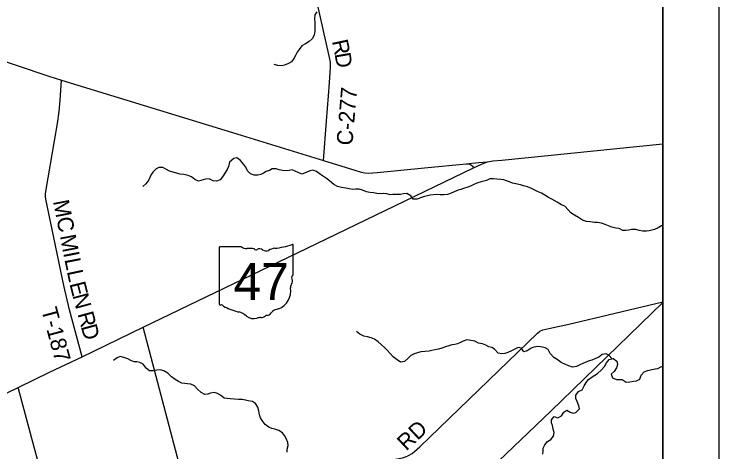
# Model space of a CAD drawing. Extents: x 0 to 34, y 0 to 22.
# Drawn here: x 7.746 to 9, y 18.489 to 19.269 of the extents above; entities that cross this region are included whole.
import ezdxf

# ---------------------------------------------------------------- set-up
doc = ezdxf.new("R2010")
doc.units = 0
for name, color, linetype in [('GM_X_Corporation', 7, 'Continuous'), ('GM_X_County_Road', 7, 'Continuous'), ('GM_X_County_Road_Text', 7, 'Continuous'), ('GM_X_Minor_River', 7, 'Continuous'), ('GM_X_Rail_Line', 7, 'Continuous'), ('GM_X_State_Location', 7, 'Continuous'), ('GM_X_State_Route', 7, 'Continuous'), ('GM_X_State_Shield', 7, 'Continuous'), ('GM_X_Township_Road', 7, 'Continuous'), ('GM_X_Township_Road_Text', 7, 'Continuous'), ('SH_Data', 7, 'Continuous')]:
    doc.layers.add(name, color=color, linetype=linetype)

msp = doc.modelspace()

# ---------------------------------------------------------------- linework, layer by layer
at = {"layer": 'GM_X_Corporation'}
msp.add_lwpolyline([(2.7052, 14.1), (8.9, 14.1), (8.9, 20.9), (3.3687, 20.9)], dxfattribs=at)
at = {"layer": 'GM_X_County_Road'}
msp.add_line((8.0553, 18.4096), (7.9758, 18.7116), dxfattribs=at)
for points in [[(8.2963, 19.0086), (8.302, 19.0784), (8.3053, 19.1235), (8.3071, 19.1474), (8.3085, 19.1645), (8.309, 19.1752), (8.3086, 19.1834), (8.3071, 19.1921), (8.2781, 19.3218), (8.2222, 19.5554), (8.2211, 19.5604), (8.2198, 19.5642), (8.2177, 19.5688), (8.2146, 19.5731), (8.2097, 19.5775), (8.182, 19.5969), (8.1775, 19.6005), (8.1738, 19.605), (8.1718, 19.6086), (8.1697, 19.6132), (8.1473, 19.6984), (8.1296, 19.7719)], [(7.5127, 19.2579), (7.8078, 19.1585), (7.8301, 19.1512), (8.1499, 19.0536), (8.2963, 19.0086), (8.3523, 18.9913), (8.3632, 18.9879), (8.37, 18.9865), (8.3767, 18.9857), (8.3918, 18.9869), (8.4764, 18.9952), (8.5503, 19.0026), (8.5542, 19.0026), (8.5566, 19.0019), (8.5586, 19.0009), (8.5604, 18.9996), (8.5617, 18.9983), (8.5629, 18.9963), (8.5634, 18.9953)], [(8.5503, 19.0026), (8.5721, 19.0049), (8.5881, 19.0061)], [(8.0553, 18.4096), (8.4281, 18.4771), (8.437, 18.4792), (8.4423, 18.4808), (8.4474, 18.4831), (8.4542, 18.4866), (8.4585, 18.4901), (8.468, 18.4988), (8.6772, 18.7011), (8.6815, 18.7044), (8.6868, 18.7067), (8.6976, 18.7094), (8.7166, 18.7135), (8.7303, 18.7166), (8.9, 18.7566)], [(7.9482, 17.7373), (7.9476, 17.7398), (7.9368, 17.7869), (7.8597, 18.12), (7.8214, 18.2877), (7.8179, 18.3039), (7.8159, 18.3198), (7.8153, 18.3322), (7.8149, 18.3594), (7.8146, 18.3659), (7.8137, 18.3742), (7.8123, 18.3822), (7.8085, 18.3979), (7.8046, 18.4124), (7.7817, 18.4979), (7.7531, 18.6039)]]:
    msp.add_lwpolyline(points, dxfattribs=at)
at = {"layer": 'GM_X_Minor_River'}
msp.add_line((8.9, 18.8932), (8.8979, 18.892), dxfattribs=at)
for points in [[(8.2843, 19.2733), (8.2809, 19.2676), (8.2805, 19.2604), (8.2812, 19.2534), (8.2812, 19.2465), (8.281, 19.2386), (8.2796, 19.2319), (8.2764, 19.2253), (8.2712, 19.2202), (8.2644, 19.216), (8.258, 19.2125), (8.253, 19.206), (8.2498, 19.2011), (8.2467, 19.1952), (8.2439, 19.1901), (8.2393, 19.1843), (8.2342, 19.1811), (8.2268, 19.1783), (8.2216, 19.1769), (8.215, 19.1777), (8.2086, 19.1795)], [(8.2774, 18.991), (8.2723, 18.9899), (8.2656, 18.9868), (8.2581, 18.9842), (8.2514, 18.9869), (8.2458, 18.9896), (8.2407, 18.9915), (8.2353, 18.9908), (8.2302, 18.9902), (8.2236, 18.9906), (8.2177, 18.9916), (8.2122, 18.9935), (8.205, 18.9935), (8.2003, 18.9905), (8.1944, 18.989), (8.1895, 18.9856), (8.1847, 18.9836), (8.1798, 18.9823), (8.1732, 18.9823), (8.1668, 18.9848), (8.1613, 18.9903), (8.1585, 18.9964), (8.1547, 19.0011), (8.1487, 19.0084), (8.1422, 19.0131), (8.1369, 19.012), (8.1293, 19.0056), (8.1274, 18.9978), (8.1249, 18.9923), (8.1211, 18.9859), (8.1169, 18.9793), (8.1123, 18.9738), (8.1061, 18.9714), (8.0998, 18.9725), (8.093, 18.9756), (8.0866, 18.9752), (8.0737, 18.9719), (8.0675, 18.9746), (8.0618, 18.9793), (8.0554, 18.9816), (8.048, 18.9832), (8.0412, 18.984), (8.0349, 18.9857), (8.029, 18.9876), (8.0224, 18.9897), (8.0169, 18.9926), (8.0103, 18.9962), (8.0037, 18.9961), (7.9988, 18.9934), (7.9934, 18.9885), (7.99, 18.9834), (7.9858, 18.9737), (7.9803, 18.9671), (7.9748, 18.962)], [(8.8979, 18.892), (8.8919, 18.8884), (8.8856, 18.8854), (8.8807, 18.8841), (8.8759, 18.8831), (8.8712, 18.8826), (8.8646, 18.8824), (8.8581, 18.8838), (8.8519, 18.8857), (8.8447, 18.8853), (8.8398, 18.8844), (8.8341, 18.8835), (8.8292, 18.8835), (8.8225, 18.8871), (8.8165, 18.8877), (8.8095, 18.8895), (8.8036, 18.8921), (8.7979, 18.8946), (8.7913, 18.8967), (8.7837, 18.8979), (8.7788, 18.8979), (8.7716, 18.8989), (8.7642, 18.8999), (8.7572, 18.9024), (8.7499, 18.9071), (8.7431, 18.9112), (8.7368, 18.9154), (8.7319, 18.9207), (8.7259, 18.9268), (8.7198, 18.9296), (8.7121, 18.9342), (8.7028, 18.9396), (8.6966, 18.9426), (8.6905, 18.9468), (8.6845, 18.9501), (8.6783, 18.9528), (8.6711, 18.9562), (8.6656, 18.9589), (8.6597, 18.9614), (8.6523, 18.9635), (8.6472, 18.9648), (8.6385, 18.9668), (8.6329, 18.9681), (8.6272, 18.9702), (8.6223, 18.9723), (8.6173, 18.9737), (8.6117, 18.9748), (8.6048, 18.9754), (8.599, 18.976), (8.5923, 18.9755), (8.5863, 18.973), (8.5772, 18.9706), (8.5694, 18.9682), (8.5639, 18.9657), (8.558, 18.9627), (8.5533, 18.961), (8.5457, 18.9588), (8.5408, 18.9569), (8.5358, 18.9554), (8.529, 18.9526), (8.5222, 18.9494), (8.517, 18.9479), (8.5108, 18.9472), (8.5042, 18.9472), (8.4983, 18.9478), (8.4918, 18.9472), (8.4865, 18.9465), (8.4814, 18.9456), (8.4761, 18.9445), (8.4691, 18.9422), (8.4628, 18.9394), (8.4562, 18.9396), (8.4517, 18.9457), (8.4445, 18.9495), (8.439, 18.9492), (8.4337, 18.948), (8.4269, 18.9479), (8.4199, 18.9479), (8.4148, 18.9475), (8.4093, 18.9489), (8.4034, 18.9495), (8.3981, 18.9491), (8.3911, 18.9497), (8.3854, 18.9511), (8.3786, 18.9513), (8.3727, 18.9528), (8.3657, 18.9553), (8.3599, 18.9573), (8.3534, 18.9573), (8.3485, 18.9569), (8.3419, 18.9577), (8.336, 18.9594), (8.3286, 18.9606), (8.3214, 18.9621), (8.3146, 18.9658), (8.3069, 18.9723), (8.3016, 18.9763), (8.2967, 18.9801), (8.2912, 18.9837), (8.284, 18.9891), (8.2774, 18.991)], [(8.8102, 18.6555), (8.804, 18.6616), (8.7991, 18.6639), (8.7923, 18.6628), (8.7862, 18.6583), (8.7794, 18.6555), (8.7741, 18.653), (8.7676, 18.6508), (8.7623, 18.6489), (8.7576, 18.647), (8.7525, 18.6446), (8.7468, 18.6414), (8.7394, 18.6406), (8.7329, 18.6426), (8.7269, 18.6449), (8.7193, 18.6489), (8.7121, 18.6538), (8.7061, 18.6575), (8.6997, 18.6649), (8.6959, 18.6717), (8.6906, 18.6748), (8.6829, 18.6765), (8.678, 18.6769), (8.6707, 18.676), (8.666, 18.6743), (8.659, 18.6694), (8.6527, 18.6677), (8.649, 18.6744), (8.6427, 18.6752), (8.638, 18.6731), (8.6309, 18.6693), (8.6243, 18.6663), (8.619, 18.6646), (8.6137, 18.6639), (8.6071, 18.6654), (8.6008, 18.6723), (8.5957, 18.6754), (8.5908, 18.6765), (8.5853, 18.6794), (8.5795, 18.6817), (8.5723, 18.6834), (8.5659, 18.6865), (8.5585, 18.688), (8.5515, 18.689), (8.545, 18.6869), (8.5401, 18.6843), (8.5351, 18.6822), (8.5302, 18.6809), (8.5245, 18.68), (8.5194, 18.6785), (8.5135, 18.6766), (8.5069, 18.674), (8.5008, 18.6725), (8.4944, 18.6712), (8.4891, 18.6699), (8.4843, 18.6688), (8.4768, 18.6682), (8.4696, 18.6675), (8.4637, 18.666), (8.4568, 18.6634), (8.4521, 18.6613), (8.4464, 18.6558), (8.4405, 18.6504), (8.4333, 18.6494), (8.4273, 18.6533), (8.4206, 18.6586), (8.415, 18.6647), (8.4095, 18.6708), (8.4048, 18.6757), (8.3999, 18.6803), (8.3939, 18.6855), (8.3871, 18.6904), (8.3812, 18.6927), (8.3746, 18.6946), (8.3679, 18.6956), (8.3608, 18.6994), (8.3549, 18.7038)], [(8.2317, 18.489), (8.2317, 18.4943), (8.2333, 18.5008), (8.2327, 18.5065), (8.2301, 18.5133), (8.2273, 18.5184), (8.2233, 18.5232), (8.2167, 18.5274), (8.2099, 18.5301), (8.2042, 18.5312), (8.1991, 18.5333), (8.1925, 18.5385), (8.1872, 18.5455), (8.1842, 18.5503), (8.1825, 18.5556), (8.1814, 18.5626), (8.1797, 18.5689), (8.1752, 18.5754), (8.1699, 18.5792), (8.1625, 18.5805), (8.1576, 18.5815), (8.1517, 18.5827), (8.1453, 18.5829), (8.1381, 18.5833), (8.1305, 18.5841), (8.125, 18.5843), (8.1197, 18.5851), (8.1133, 18.5906), (8.108, 18.5935), (8.1016, 18.5954), (8.0955, 18.5943), (8.0904, 18.5922), (8.0855, 18.5917), (8.0789, 18.5953), (8.0723, 18.6012), (8.0668, 18.6069), (8.0604, 18.6102), (8.0543, 18.6108), (8.0494, 18.6112), (8.0445, 18.6119), (8.0384, 18.6146), (8.0327, 18.6184), (8.0261, 18.6234), (8.0195, 18.6297), (8.0125, 18.6341), (8.0059, 18.6358), (7.9997, 18.6353), (7.9938, 18.6338), (7.987, 18.6336), (7.9811, 18.6386), (7.9756, 18.6458), (7.9694, 18.6485), (7.9645, 18.6496), (7.9596, 18.6497), (7.9533, 18.6523), (7.948, 18.6554), (7.9414, 18.6575), (7.9346, 18.6591), (7.9295, 18.657), (7.9226, 18.6523)], [(8.6869, 18.4855), (8.6871, 18.4912), (8.6875, 18.4959), (8.6901, 18.5022), (8.6951, 18.5078), (8.7012, 18.5114), (8.7059, 18.5173), (8.7069, 18.5239), (8.7052, 18.53), (8.7037, 18.5366), (8.702, 18.5414), (8.7023, 18.5463), (8.7068, 18.5526), (8.7134, 18.5501), (8.7201, 18.5538), (8.7239, 18.5605), (8.7296, 18.5637), (8.7356, 18.5604), (8.7408, 18.5587), (8.7457, 18.5598), (8.7518, 18.5664), (8.7508, 18.5717), (8.7477, 18.579), (8.7452, 18.5843), (8.7456, 18.5907), (8.75, 18.5972), (8.7568, 18.6002), (8.7601, 18.607), (8.7641, 18.613), (8.7679, 18.6182), (8.7742, 18.6232), (8.7793, 18.6263), (8.784, 18.6293), (8.7903, 18.6349), (8.7964, 18.6414), (8.8002, 18.648), (8.8048, 18.6541), (8.8116, 18.6559), (8.8182, 18.6512), (8.8193, 18.6451), (8.818, 18.6392), (8.8136, 18.6328), (8.8083, 18.6277), (8.8109, 18.6214), (8.8175, 18.6183), (8.8224, 18.6187), (8.8281, 18.6185), (8.8349, 18.6139), (8.8414, 18.6141), (8.8482, 18.6156), (8.8535, 18.6163), (8.8592, 18.6193), (8.8615, 18.6261), (8.8672, 18.6322), (8.8736, 18.6346)], [(8.8736, 18.6346), (8.8805, 18.6363), (8.8865, 18.6372), (8.8913, 18.6383), (8.8964, 18.641), (8.9, 18.6422)]]:
    msp.add_lwpolyline(points, dxfattribs=at)
at = {"layer": 'GM_X_Rail_Line'}
msp.add_lwpolyline([(5.2658, 15.2105), (5.3357, 15.2914), (5.4094, 15.3777), (5.4899, 15.4707), (5.6406, 15.6155), (5.8342, 15.8017), (6.1881, 16.1426), (6.4582, 16.4022), (6.7352, 16.6681), (7.0136, 16.9364), (7.2435, 17.1561), (7.4421, 17.3509), (7.6263, 17.5265), (7.9296, 17.8183), (8.0773, 17.9623), (8.4366, 18.3089), (8.7009, 18.5622), (8.9, 18.7553)], dxfattribs=at)
at = {"layer": 'GM_X_State_Route'}
msp.add_lwpolyline([(7.6544, 18.5581), (7.6984, 18.5781), (7.7531, 18.6039), (7.8091, 18.6312), (7.8668, 18.6586), (7.9758, 18.7116), (8.2503, 18.8438), (8.5634, 18.9953), (8.5774, 19.0021), (8.5832, 19.0045), (8.5881, 19.0061), (8.5979, 19.0076), (8.6135, 19.0091), (8.9, 19.038)], dxfattribs=at)
at = {"layer": 'GM_X_State_Shield'}
for p, q in [((8.1105, 18.8531), (8.1105, 18.753)), ((8.1504, 18.8548), (8.1118, 18.8548)), ((8.2424, 18.8049), (8.2424, 18.8573)), ((8.2424, 18.805), (8.2424, 18.8049))]:
    msp.add_line(p, q, dxfattribs=at)
for centre, radius, start, end in [((8.112, 18.8533), 0.00153, 98.1301, 188.1301), ((8.1596, 18.8664), 0.0148, 231.6195, 271.1119), ((8.1646, 18.7986), 0.0532, 80.4867, 94.9883), ((8.1766, 18.8538), 0.00427, 219.7921, 297.1024), ((8.1829, 18.8422), 0.00889, 54.4667, 119.1411), ((8.2132, 18.8242), 0.0281, 97.3462, 120.7689), ((8.1954, 18.9912), 0.1398, 275.8445, 288.9065), ((8.2409, 18.8575), 0.00147, 351.8621, 97.738), ((8.1944, 18.8581), 0.0107, 233.8562, 294.8282), ((8.242, 18.8011), 0.00227, 107.944, 210.337), ((8.2276, 18.7945), 0.0136, 340.033, 23.6496), ((8.2408, 18.8047), 0.00157, 289.6038, 7.7341), ((8.2476, 18.783), 0.00992, 136.8065, 186.9296), ((8.2032, 18.7764), 0.035, 292.3089, 8.9858), ((8.1121, 18.7528), 0.00154, 171.9584, 258.3066), ((8.1123, 18.763), 0.0118, 267.339, 280.6039), ((8.1147, 18.7472), 0.00424, 29.7484, 93.2717), ((8.1682, 18.8371), 0.101, 240.4129, 257.1985), ((8.1381, 18.7081), 0.0316, 47.1842, 75.836), ((8.218, 18.7249), 0.0192, 94.4031, 142.5768), ((8.1723, 18.7468), 0.02, 230.7004, 286.2918), ((8.1839, 18.7122), 0.0165, 85.6951, 111.2099), ((8.1853, 18.7393), 0.0107, 268.777, 315.5493), ((8.195, 18.7296), 0.00301, 65.7517, 132.6484), ((8.1937, 18.7433), 0.0113, 282.8732, 323.2771)]:
    msp.add_arc(centre, radius, start, end, dxfattribs=at)
at = {"layer": 'GM_X_Township_Road'}
msp.add_lwpolyline([(7.8668, 18.6586), (7.8446, 18.7427), (7.8341, 18.7856), (7.8023, 18.9393), (7.8018, 18.9436), (7.802, 18.9489), (7.803, 18.957), (7.8176, 19.0433), (7.823, 19.0745), (7.8263, 19.0959), (7.8281, 19.1157), (7.8301, 19.1512)], dxfattribs=at)
at = {"layer": 'SH_Data'}
for p, q in [((9, 21), (9, 14)), ((8.9, 20.9), (8.9, 14.1))]:
    msp.add_line(p, q, dxfattribs=at)

# ---------------------------------------------------------------- texts
at = {"layer": 'GM_X_County_Road_Text'}
for s, height, rotation, p in [('R', 0.0284, 282.0631, (8.3112, 19.2209)), ('D', 0.0284, 279.7438, (8.316, 19.1984)), ('C-277', 0.02841, 85.3045, (8.3478, 19.0345)), ('RD', 0.02841, 43.0911, (8.4437, 18.4902))]:
    msp.add_text(s, height=height, rotation=rotation, dxfattribs=at).set_placement(p)
at = {"layer": 'GM_X_State_Location'}
msp.add_text('47', height=0.0000947, rotation=0, dxfattribs=at).set_placement((8.1511, 18.7895))
for s in ['s', 'r']:
    msp.add_text(s, height=0.0000947, dxfattribs=at).set_placement((8.175, 18.7964))
at = {"layer": 'GM_X_State_Shield'}
msp.add_text('47', height=0.06592, dxfattribs=at).set_placement((8.1365, 18.7601))
at = {"layer": 'GM_X_Township_Road_Text'}
for s, height, rotation, p in [('M', 0.0284, 281.1252, (7.815, 18.9357)), ('C', 0.0284, 281.1232, (7.821, 18.9054)), ('M', 0.0284, 281.1252, (7.8271, 18.874)), ('I', 0.0284, 281.1232, (7.8331, 18.8437)), ('L', 0.0284, 281.1461, (7.8354, 18.8322)), ('L', 0.0284, 282.0771, (7.8396, 18.8109)), ('E', 0.0284, 283.9552, (7.8442, 18.7891)), ('N', 0.0284, 285.1703, (7.8495, 18.7679)), ('T-187', 0.02841, 285.0585, (7.7939, 18.7428)), ('R', 0.0284, 285.212, (7.8584, 18.7353)), ('D', 0.0284, 285.2154, (7.8645, 18.7128))]:
    msp.add_text(s, height=height, rotation=rotation, dxfattribs=at).set_placement(p)

doc.saveas('drawing.dxf')
